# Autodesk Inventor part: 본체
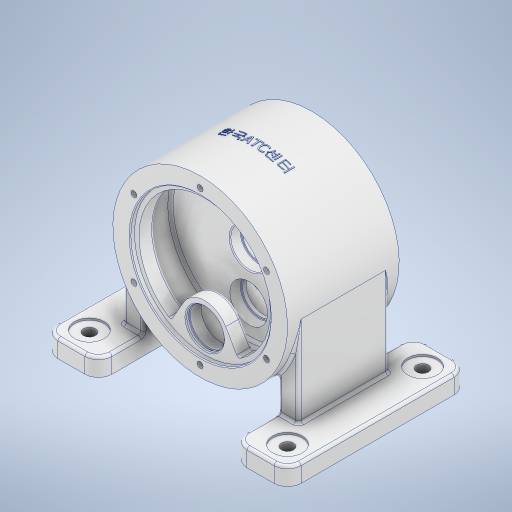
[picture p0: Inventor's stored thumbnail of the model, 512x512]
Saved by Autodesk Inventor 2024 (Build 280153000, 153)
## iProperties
Created: 2025-12
Part Number: 본체
Material: 알루미늄 6061
Document SubType Name: Modeling
Designer: Eud07
Density: 2.7 g/cm^3
Appearance: 알루미늄 - 평지
Mass: 5626.68 g
Surface Area: 3056.66 cm^2
Volume: 2083.95 cm^3
Author: Eud07
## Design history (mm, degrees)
sketch "스케치1"
  geometry: L1 (-97, -62)-(97, -62); L2 (97, -62)-(97, 62); L3 (97, 62)-(-97, 62); L4 (-97, 62)-(-97, -62); L5 (-97, -62)-(97, 62); L6 (97, -62)-(-97, 62); L7 (0, 62)-(0, -62); L8 (78, 62)-(78, 57); L9 (78, 57)-(73, 57); L10 (73, 57)-(73, 40); L11 (73, 40)-(87, 40); L12 (87, 40)-(87, 8); L13 (87, 8)-(0, 8); L14 (97, 0)-(0, 0); L15 (78, -62)-(78, -57); L16 (78, -57)-(73, -57); L17 (73, -57)-(73, -40); L18 (73, -40)-(87, -40); L19 (87, -40)-(87, -8); L20 (87, -8)-(0, -8); 2 further points
  constraints: 40 end point, 7 symmetric about line, 6 perpendicular, 5 midpoint, 2 horizontal, 2 parallel, 2 point on line, 1 vertical
  dimensions: "d0" = 124 distance of L1.end L2.end; "d1" = 97 distance between parallel lines of L7 L2; "d2" = 22 distance between parallel lines of L11 L3; "d3" = 5 distance of L8.start L8.end; "d4" = 32 distance of L11.end L12.end; "d5" = 78 distance between parallel lines of L7 L8; "d6" = 73 distance between parallel lines of L7 L10; "d7" = 87 distance between parallel lines of L7 L12
revolve "회전1" sketch "스케치1" stored, may be unused: angle "d8" = 90 deg
feature "면 삭제1"
sketch "스케치2" dims "d10" = 54
  geometry: L1 (-23.383, -39)-(-61.06, -104.259); L2 (0, 0)-(0, -116.93); L3 (23.383, -39)-(61.06, -104.259); C1 r 73 at (0, 0); 5 further points
  constraints: 6 end point, 2 symmetric about line, 1 centre point, 1 coincident, 1 vertical, 1 vertical alignment, 4 other
  dimensions: "d9" = 146 diameter of C1; "d11" = 52.5 distance of point (0, -52.5) point (0, 0); "d12" = 30 deg angle of L2 L1
extrude "돌출1" cut sketch "스케치2" distance "d13" = 17; taper "d14" = 0 deg
sketch "스케치3"
  geometry: C1 r 21 at (0, 0); C2 r 21 at (0, -52.5); C3 r 19 at (0, 0); C4 r 19 at (0, -52.5); A1 r 27 centre (0, -52.5) between (23.383, -39) and (-23.383, -39) reference; 1 further point
  constraints: 4 centre point, 3 coincident, 1 concentric
  dimensions: "d15" = 42 diameter of C1; "d16" = 42 diameter of C2; "d17" = 38 diameter of C3; "d18" = 38 diameter of C4
extrude "돌출2" cut sketch "스케치3" distance "d19" = 66; taper "d20" = 0 deg
extrude "돌출3" cut sketch "스케치3" extent not by distance; stored distance "d21" = 0; taper "d22" = 0 deg
sketch "스케치4"
  geometry: L1 (-52.5, 76.931)-(-52.5, 27.612); L2 (-87, 8)-(87, 8) reference; L3 (-73.5, 57)-(-31.5, 57) reference; L4 (-31.5, 57)-(-31.5, 40) reference; L5 (-31.5, 53.95)-(-30.25, 53.95); L6 (-30.25, 53.95)-(-30.25, 52); L7 (-30.25, 52)-(-31.5, 52); L8 (-31.5, 52)-(-31.5, 53.95); L9 (-39, 40)-(-25.5, 40) reference; 2 further points
  constraints: 10 end point, 2 parallel, 2 perpendicular, 1 horizontal, 1 point on line
  dimensions: "d23" = 21 distance from line of L3.end L1; "d24" = 1.95 distance of L5.end L6.end; "d25" = 12 distance between parallel lines of L9 L7; "d26" = 22.25 distance between parallel lines of L1 L6
revolve "회전2" sketch "스케치4" stored, may be unused: angle "d27" = 90 deg
node "작업 평면1"
sketch "스케치6"
  geometry: L1 (135, -100)-(75, -100); L2 (75, -100)-(75, 100); L3 (75, 100)-(135, 100); L4 (135, 100)-(135, -100); L5 (135, -100)-(75, 100); L6 (75, -100)-(135, 100); L7 (75, -50)-(97, -50); L8 (97, -50)-(97, 50); L9 (97, 50)-(75, 50); L10 (75, 50)-(75, -50); 3 further points
  constraints: 20 end point, 4 parallel, 2 horizontal, 2 midpoint, 2 perpendicular, 1 horizontal alignment, 1 point on line
  dimensions: "d29" = 60 distance of L2.end L3.end; "d30" = 75 distance from line of point (0, 0) L2; "d31" = 200 distance of L3.end L1.start; "d32" = 22 distance of L8.end L9.end; "d33" = 100 distance of L7.end L8.end; "d34" = 50 distance from line of point (0, 0) L7
extrude "돌출4" join sketch "스케치6" distance "d35" = 20; taper "d36" = 0 deg
extrude "돌출5" join sketch "스케치6" stored distance "d37" = 20; taper "d38" = 0 deg
fillet "모깎기1" dims "d39" = 15
sketch "스케치7"
  geometry: L1 (-135, 85)-(-135, -85) reference; L2 (73, -57)-(-73, -57) reference; 6 further points
  constraints: 2 midpoint
  dimensions: "d40" = 75 vertical distance of point (-135, 0) point (-110, 75); "d41" = 110 horizontal distance of point (0, -57) point (-110, 75)
hole "구멍1" sketch "스케치7" at (-110, 75) diameter "d42" = 13.5; stored, may be unused: countersink angle "d46" = 90 deg, drill point angle "d48" = 118 deg; dims "d43" = 6, "d44" = 33, "d45" = 2, "d47" = 8
sketch "스케치8"
  geometry: L1 (-75, -120)-(-75, -100) reference; L2 (-75, -112)-(-36.6, -89.83); L3 (-75, -100)-(-75, -61.514) reference; L4 (-75, -120)-(-90, -120) reference; A1 r 97 centre (0, 0) between (-36.6, -89.83) and (-75, -61.514) reference; 2 further points
  constraints: 2 end point, 1 coincident, 1 point on circle, 1 point on line
  dimensions: "d49" = 60 deg angle of L2 L3; "d50" = 8 distance from line of L4 point (-75, -112)
feature "리브1" sketch "스케치8" dims "d51" = 1, "d52" = 12, "d53" = 0, "d54" = 0, "d55" = 1, "d56" = 1
sketch "스케치9"
  geometry: 2 further points
  constraints: 1 vertical alignment
  dimensions: "d57" = 85 distance of point (0, 0) point (0, 85)
hole "구멍2" sketch "스케치9" at (0, 85) diameter "d58" = 6.647; stored, may be unused: countersink angle "d62" = 90 deg, drill point angle "d64" = 118 deg; dims "d59" = 16, "d60" = 33, "d61" = 2, "d63" = 18
node "작업 평면2"
sketch "스케치10"
  geometry: 2 further points
  constraints: 1 coincident, 1 other
feature "엠보싱1" sketch "스케치10" dims "d0" = 124, "d1" = 97, "d2" = 22, "d3" = 5, "d4" = 32, "d5" = 78, "d6" = 73, "d7" = 87, "d69" = 0.5, "d70" = 0
fillet "모깎기2" dims "d71" = 0.6
fillet "모깎기3" dims "d72" = 3
fillet "모깎기4" dims "d73" = 3
fillet "모깎기5" dims "d74" = 3
chamfer "모따기1" distance "d75" = 1; stored, may be unused: second distance "d76" = 2, angle "d77" = 45 deg
fillet "모깎기6" dims "d78" = 3
fillet "모깎기7" dims "d79" = 3
chamfer "모따기2" distance "d80" = 1; stored, may be unused: second distance "d81" = 2, angle "d82" = 45 deg
chamfer "모따기3" distance "d83" = 1; stored, may be unused: second distance "d84" = 2, angle "d85" = 45 deg
node "솔리드1"
mirror "미러1"
mirror "미러2"
pattern_circular "원형 패턴1" dims angle "d66" = 360 deg
mirror "미러3"
feature "A9D066F2-1C7D-4E18-AEED-F7BC21143FA4" dims "d58" = 6.647, "d59" = 16, "d60" = 33, "d61" = 2, "d62" = 90 deg, "d63" = 18, "d64" = 118 deg
other parameters: "d68" = 160.25
